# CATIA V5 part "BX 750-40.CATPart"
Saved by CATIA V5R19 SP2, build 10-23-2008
Part number: BX 750-40
Bounding box of the stored display mesh (mm): x -47.487 to 47.487, y -47.487 to 47.487, z 0 to 210
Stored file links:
  C:\Users\Bora\Desktop\3D Katı model\BX serisi\BX 750\BX 750-40.CATPart
  C:\Program Files\Dassault Systemes\B19\intel_a\reffiles\standard\MetricThickPitch.txt
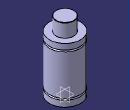
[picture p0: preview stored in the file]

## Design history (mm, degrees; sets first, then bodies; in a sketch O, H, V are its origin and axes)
Body1 (main body)
  Sketch1 on yz-plane, origin (0, 0, 0), H (0, 1, 0), V (0, 0, 1)
    point P1 (47.5, 146.5)
    point P2 (47.5, 151.5)
    arc A1 centre (47.5, 149) radius 2.5 from (47.5, 151.5) to (47.5, 146.5) ccw
    point P3 (47.5, 18.5)
    point P4 (47.5, 23.5)
    arc A2 centre (47.5, 21) radius 2.5 from (47.5, 23.5) to (47.5, 18.5) ccw
    point P5 (47.5, 151.5)
    line L1 (47.5, 169) -> (47.5, 151.5)
    point P8 (27.5, 209)
    line L2 (27.5, 209) -> (27.5, 169)
    point P10 (27.5, 209)
    arc A3 centre (26.5, 209) radius 1 from (27.5, 209) to (26.5, 210) ccw
    point P11 (47.5, 23.5)
    point P12 (47.5, 146.5)
    line L3 (47.5, 146.5) -> (47.5, 23.5)
    point P14 (47.5, 18.5)
    line L4 (47.5, 18.5) -> (47.5, 0)
    line L5 (26.5, 210) -> (0, 210)
    point P15 (0, 210)
    line L6 (27.5, 169) -> (47.5, 169)
    line L7 (47.5, 0) -> (0, 0)
    tangency: L5 A3
    coincidence: P15 V, P1 P12, P2 P5, P3 P14, P4 P11, P8 P10
    horizontal: L6 H, L7 H
  Shaft1: profile Sketch1, axis Sketch1.V, angle 360
  Sketch2 on face of Shaft1 from Sketch1.L7, origin (0, 0, 0), H (1, 0, 0), V (0, -1, 0)
    point P1 (25, 0)
    distance P1 V = 25
  Hole1: placed by Sketch2, at (25, 0, 0) direction (0, 0, 1), diameter 6.647, depth 10, threaded "M8", thread diameter 8, thread depth 10, pitch 1.25
  CircPattern1: of Hole1, instances 4, angular step 90, axis from xy-plane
